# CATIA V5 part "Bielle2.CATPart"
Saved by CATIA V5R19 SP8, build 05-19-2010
Part number: Bielle2
Bounding box of the stored display mesh (mm): x 0 to 50, y -119.864 to 119.864, z -829.809 to 259.809
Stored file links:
  C:\Users\ThinkMotion\Desktop\EU_thinkMotion\iao\IAO_MMS_Groupe3\gdespas\projet_Thinkmotion_GDESPAS\projet Thinkmotion GDESPAS\Assemblage gdespas\Bielle2.CATPart
  C:\Users\ThinkMotion\Desktop\EU_thinkMotion\iao\IAO_MMS_Groupe3\gdespas\projet_Thinkmotion_GDESPAS\projet Thinkmotion GDESPAS\Assemblage gdespas\Assemblage IAO.CATProduct
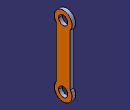
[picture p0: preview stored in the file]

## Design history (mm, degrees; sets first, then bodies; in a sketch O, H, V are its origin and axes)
External parameters (linked from other documents)
  External.diam_axe = 0.126
  External.entraxe_b2 = 0.85
Body1 (main body)
  Sketch1 on yz-plane, origin (0, 0, 0), H (0, 1, 0), V (0, 0, 1)
    arc A1 centre (0, -710) radius 120 from (-97, -639.353) to (97, -639.353) ccw
    point P1 (0, -710)
    arc A2 centre (0, 140) radius 120 from (97, 69.353) to (-97, 69.353) ccw
    point P2 (0, 140)
    line L1 (-97, 69.353) -> (-97, -639.353)
    line L2 (97, 69.353) -> (97, -639.353)
    reference intersected line E1 through (0, 0) direction (-1, 0) from xy-plane
    circle A3 centre (0, 140) radius 63
    point P7 (0, 77)
    circle A4 centre (0, -710) radius 63
    radius A1 = 120
    radius A2 = 120
    distance P2 P1 = 850 {= External.entraxe_b2}
    distance L2 L1 = 194
    distance L1 V = 97
    distance P1 E1 = 710
    radius A4 = 63 {= External.diam_axe /2}
    radius A3 = 63 {= External.diam_axe /2}
    coincidence: P1 V, P2 V, A3 P7, P7 V
    vertical: L1 V, L2 V
  Pad1: profile Sketch1, direction (1, 0, 0), length 50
